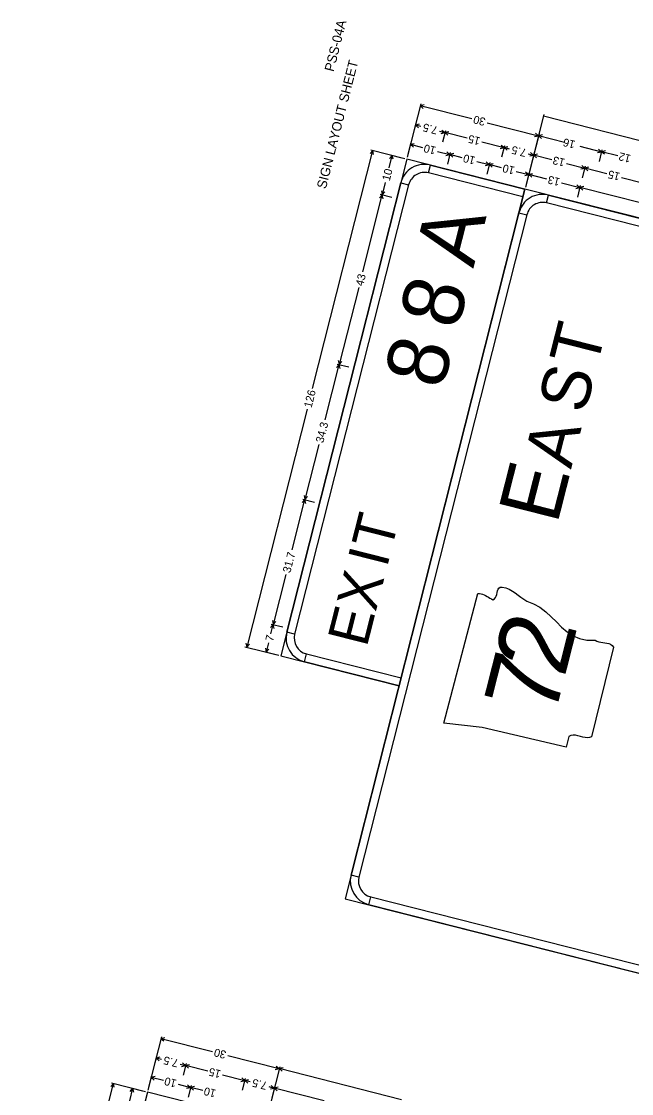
# Model space of a CAD drawing. Extents: x 670010 to 670131, y 737834 to 738002.
# Drawn here: x 670014.7 to 670052.3, y 737936.3 to 738002.2 of the extents above; entities that cross this region are included whole.
import ezdxf

# ---------------------------------------------------------------- set-up
doc = ezdxf.new("R2010")
doc.units = 0
doc.layers.add('R_Border', color=7, linetype='Continuous')
doc.layers.add('R_SIGN', color=7, linetype='Continuous')

msp = doc.modelspace()

# ---------------------------------------------------------------- linework, layer by layer
at = {"layer": 'R_SIGN'}
for p, q in [((670039.295, 737997.146), (670038.463, 737993.866)), ((670039.505, 737997.079), (670039.265, 737997.027)), ((670042.428, 737996.224), (670039.265, 737997.027)), ((670039.451, 737996.866), (670039.265, 737997.027)), ((670043.371, 737995.985), (670046.535, 737995.183)), ((670046.867, 737996.495), (670045.733, 737992.023)), ((670065.094, 737991.745), (670046.837, 737996.376)), ((670038.993, 737995.953), (670038.811, 737995.238)), ((670039.203, 737995.887), (670038.962, 737995.834)), ((670039.302, 737995.748), (670038.962, 737995.834)), ((670039.149, 737995.673), (670038.962, 737995.834)), ((670040.44, 737995.459), (670040.78, 737995.373)), ((670040.54, 737995.321), (670040.78, 737995.373)), ((670040.594, 737995.534), (670040.78, 737995.373)), ((670040.81, 737995.492), (670040.629, 737994.777)), ((670041.02, 737995.426), (670040.78, 737995.373)), ((670042.146, 737995.027), (670040.78, 737995.373)), ((670040.966, 737995.212), (670040.78, 737995.373)), ((670046.349, 737995.344), (670046.535, 737995.183)), ((670038.69, 737994.761), (670038.509, 737994.045)), ((670038.9, 737994.694), (670038.66, 737994.642)), ((670043.049, 737994.798), (670044.415, 737994.451)), ((670046.565, 737995.302), (670045.733, 737992.023)), ((670046.294, 737995.13), (670046.535, 737995.183)), ((670046.775, 737995.236), (670046.535, 737995.183)), ((670048.141, 737994.775), (670046.535, 737995.183)), ((670046.721, 737995.022), (670046.535, 737995.183)), ((670032.638, 737979.655), (670036.346, 737994.276)), ((670036.185, 737994.09), (670036.346, 737994.276)), ((670036.227, 737994.307), (670038.314, 737993.777)), ((670036.399, 737994.036), (670036.346, 737994.276)), ((670037.419, 737994.004), (670038.135, 737993.823)), ((670039.421, 737994.448), (670038.66, 737994.642)), ((670038.846, 737994.481), (670038.66, 737994.642)), ((670040.322, 737994.22), (670041.083, 737994.027)), ((670040.843, 737993.974), (670041.083, 737994.027)), ((670040.897, 737994.188), (670041.083, 737994.027)), ((670041.113, 737994.146), (670040.932, 737993.431)), ((670041.324, 737994.08), (670041.083, 737994.027)), ((670041.845, 737993.834), (670041.083, 737994.027)), ((670041.269, 737993.866), (670041.083, 737994.027)), ((670044.174, 737994.399), (670044.415, 737994.451)), ((670044.229, 737994.612), (670044.415, 737994.451)), ((670044.445, 737994.57), (670044.264, 737993.855)), ((670044.445, 737994.57), (670044.264, 737993.855)), ((670044.655, 737994.504), (670044.415, 737994.451)), ((670044.755, 737994.365), (670044.415, 737994.451)), ((670044.601, 737994.291), (670044.415, 737994.451)), ((670045.892, 737994.077), (670046.232, 737993.99)), ((670045.992, 737993.938), (670046.232, 737993.99)), ((670046.046, 737994.151), (670046.232, 737993.99)), ((670046.262, 737994.109), (670046.081, 737993.394)), ((670046.262, 737994.109), (670046.081, 737993.394)), ((670046.473, 737994.043), (670046.232, 737993.99)), ((670047.353, 737993.706), (670046.232, 737993.99)), ((670046.418, 737993.83), (670046.232, 737993.99)), ((670049.079, 737994.538), (670050.406, 737994.201)), ((670050.165, 737994.148), (670050.406, 737994.201)), ((670050.219, 737994.362), (670050.406, 737994.201)), ((670050.436, 737994.32), (670050.254, 737993.605)), ((670050.646, 737994.254), (670050.406, 737994.201)), ((670051.411, 737993.946), (670050.406, 737994.201)), ((670050.592, 737994.04), (670050.406, 737994.201)), ((670038.433, 737993.747), (670030.689, 737963.214)), ((670037.346, 737993.213), (670037.539, 737993.974)), ((670037.378, 737993.788), (670037.539, 737993.974)), ((670037.591, 737993.734), (670037.539, 737993.974)), ((670045.703, 737991.903), (670038.433, 737993.747)), ((670039.764, 737992.894), (670039.887, 737993.378)), ((670042.745, 737993.605), (670043.506, 737993.412)), ((670043.266, 737993.36), (670043.506, 737993.412)), ((670043.32, 737993.573), (670043.506, 737993.412)), ((670043.537, 737993.532), (670043.355, 737992.816)), ((670043.537, 737993.532), (670043.355, 737992.816)), ((670043.747, 737993.465), (670043.506, 737993.412)), ((670044.268, 737993.219), (670043.506, 737993.412)), ((670043.693, 737993.252), (670043.506, 737993.412)), ((670048.256, 737993.477), (670049.376, 737993.193)), ((670049.19, 737993.354), (670049.376, 737993.193)), ((670045.168, 737992.991), (670045.93, 737992.798)), ((670045.689, 737992.745), (670045.93, 737992.798)), ((670045.744, 737992.958), (670045.93, 737992.798)), ((670045.96, 737992.917), (670045.779, 737992.201)), ((670045.96, 737992.917), (670045.779, 737992.201)), ((670046.17, 737992.85), (670045.93, 737992.798)), ((670047.05, 737992.514), (670045.93, 737992.798)), ((670046.116, 737992.637), (670045.93, 737992.798)), ((670049.136, 737993.14), (670049.376, 737993.193)), ((670049.406, 737993.312), (670049.225, 737992.597)), ((670049.617, 737993.245), (670049.376, 737993.193)), ((670050.742, 737992.846), (670049.376, 737993.193)), ((670049.563, 737993.032), (670049.376, 737993.193)), ((670037.117, 737992.312), (670036.924, 737991.551)), ((670038.064, 737992.293), (670038.549, 737992.17)), ((670047.953, 737992.285), (670049.074, 737992)), ((670048.888, 737992.161), (670049.074, 737992)), ((670049.104, 737992.12), (670048.922, 737991.404)), ((670049.314, 737992.053), (670049.074, 737992)), ((670051.645, 737992.617), (670053.011, 737992.271)), ((670045.703, 737991.903), (670034.64, 737948.284)), ((670035.724, 737986.819), (670036.924, 737991.551)), ((670036.763, 737991.365), (670036.924, 737991.551)), ((670036.805, 737991.581), (670037.52, 737991.399)), ((670036.805, 737991.581), (670037.52, 737991.399)), ((670036.872, 737991.791), (670036.924, 737991.551)), ((670037.085, 737991.737), (670036.924, 737991.551)), ((670036.977, 737991.31), (670036.924, 737991.551)), ((670037.959, 737961.37), (670045.703, 737991.903)), ((670083.506, 737982.316), (670045.703, 737991.903)), ((670047.034, 737991.05), (670047.157, 737991.535)), ((670048.833, 737991.948), (670049.074, 737992)), ((670052.961, 737991.015), (670049.074, 737992)), ((670049.26, 737991.84), (670049.074, 737992)), ((670045.334, 737990.449), (670045.819, 737990.326)), ((670035.478, 737985.851), (670034.278, 737981.119)), ((670033.418, 737977.729), (670034.278, 737981.119)), ((670034.118, 737980.932), (670034.278, 737981.119)), ((670034.159, 737981.149), (670034.875, 737980.967)), ((670034.226, 737981.359), (670034.278, 737981.119)), ((670034.439, 737981.305), (670034.278, 737981.119)), ((670034.331, 737980.878), (670034.278, 737981.119)), ((670032.311, 737978.365), (670028.602, 737963.743)), ((670033.033, 737976.209), (670032.173, 737972.819)), ((670032.121, 737973.059), (670032.173, 737972.819)), ((670032.334, 737973.005), (670032.173, 737972.819)), ((670031.392, 737969.737), (670032.173, 737972.819)), ((670032.013, 737972.633), (670032.173, 737972.819)), ((670032.054, 737972.849), (670032.77, 737972.668)), ((670032.226, 737972.578), (670032.173, 737972.819)), ((670031.007, 737968.219), (670030.225, 737965.137)), ((670040.721, 737959.068), (670042.797, 737967.042)), ((670042.797, 737967.042), (670042.901, 737967.041)), ((670042.797, 737967.042), (670042.797, 737967.042)), ((670042.901, 737967.041), (670043.002, 737967.024)), ((670043.002, 737967.024), (670043.098, 737966.996)), ((670043.098, 737966.996), (670043.192, 737966.96)), ((670043.936, 737966.883), (670043.966, 737966.991)), ((670043.966, 737966.991), (670043.99, 737967.101)), ((670043.99, 737967.101), (670044.015, 737967.207)), ((670044.015, 737967.207), (670044.05, 737967.301)), ((670044.05, 737967.301), (670044.104, 737967.377)), ((670044.104, 737967.377), (670044.182, 737967.428)), ((670044.182, 737967.428), (670044.295, 737967.443)), ((670044.295, 737967.443), (670044.527, 737967.388)), ((670044.527, 737967.388), (670044.736, 737967.304)), ((670044.736, 737967.304), (670044.928, 737967.197)), ((670044.928, 737967.197), (670045.105, 737967.075)), ((670045.105, 737967.075), (670045.279, 737966.946)), ((670043.192, 737966.96), (670043.284, 737966.915)), ((670043.284, 737966.915), (670043.372, 737966.867)), ((670043.372, 737966.867), (670043.462, 737966.813)), ((670043.462, 737966.813), (670043.548, 737966.761)), ((670043.548, 737966.761), (670043.634, 737966.71)), ((670043.634, 737966.71), (670043.721, 737966.661)), ((670043.721, 737966.661), (670043.822, 737966.711)), ((670043.822, 737966.711), (670043.891, 737966.788)), ((670043.891, 737966.788), (670043.936, 737966.883)), ((670045.279, 737966.946), (670045.45, 737966.815)), ((670045.45, 737966.815), (670045.627, 737966.689)), ((670045.627, 737966.689), (670045.813, 737966.577)), ((670045.813, 737966.577), (670046.013, 737966.481)), ((670046.013, 737966.481), (670046.234, 737966.414)), ((670046.234, 737966.414), (670046.624, 737966.196)), ((670046.624, 737966.196), (670046.977, 737965.924)), ((670046.977, 737965.924), (670047.309, 737965.619)), ((670030.064, 737964.951), (670030.225, 737965.137)), ((670030.081, 737964.569), (670030.225, 737965.137)), ((670030.106, 737965.167), (670030.821, 737964.986)), ((670030.172, 737965.377), (670030.225, 737965.137)), ((670030.386, 737965.323), (670030.225, 737965.137)), ((670030.277, 737964.897), (670030.225, 737965.137)), ((670047.309, 737965.619), (670047.633, 737965.298)), ((670047.633, 737965.298), (670047.956, 737964.983)), ((670031.543, 737964.545), (670031.058, 737964.668)), ((670047.956, 737964.983), (670048.294, 737964.693)), ((670048.294, 737964.693), (670048.657, 737964.45)), ((670048.657, 737964.45), (670049.058, 737964.27)), ((670028.483, 737963.773), (670030.57, 737963.244)), ((670028.55, 737963.983), (670028.602, 737963.743)), ((670028.763, 737963.929), (670028.602, 737963.743)), ((670029.742, 737963.681), (670029.795, 737963.441)), ((670029.939, 737964.008), (670029.795, 737963.441)), ((670049.058, 737964.27), (670049.506, 737964.174)), ((670049.506, 737964.174), (670050.015, 737964.185)), ((670051.141, 737963.753), (670049.794, 737958.233)), ((670050.015, 737964.185), (670050.123, 737964.116)), ((670050.123, 737964.116), (670050.241, 737964.071)), ((670050.241, 737964.071), (670050.363, 737964.044)), ((670050.363, 737964.044), (670050.49, 737964.028)), ((670050.49, 737964.028), (670050.615, 737964.014)), ((670050.615, 737964.014), (670050.738, 737963.998)), ((670050.738, 737963.998), (670050.857, 737963.971)), ((670050.857, 737963.971), (670050.962, 737963.926)), ((670050.962, 737963.926), (670051.06, 737963.856)), ((670051.06, 737963.856), (670051.141, 737963.753)), ((670029.675, 737963.471), (670030.391, 737963.289)), ((670029.955, 737963.627), (670029.795, 737963.441)), ((670030.689, 737963.214), (670037.959, 737961.37)), ((670032.143, 737962.845), (670032.266, 737963.33)), ((670037.959, 737961.37), (670037.959, 737961.37)), ((670043.074, 737958.815), (670040.721, 737959.068)), ((670048.239, 737957.602), (670043.074, 737958.815)), ((670048.401, 737958.244), (670048.239, 737957.602)), ((670048.53, 737958.311), (670048.401, 737958.244)), ((670048.667, 737958.336), (670048.53, 737958.311)), ((670048.81, 737958.33), (670048.667, 737958.336)), ((670048.96, 737958.303), (670048.81, 737958.33)), ((670049.109, 737958.264), (670048.96, 737958.303)), ((670049.26, 737958.222), (670049.109, 737958.264)), ((670049.404, 737958.187), (670049.26, 737958.222)), ((670049.543, 737958.172), (670049.404, 737958.187)), ((670049.675, 737958.183), (670049.543, 737958.172)), ((670049.794, 737958.233), (670049.675, 737958.183)), ((670035.494, 737949.615), (670035.009, 737949.738)), ((670034.64, 737948.284), (670072.443, 737938.697)), ((670036.094, 737947.916), (670036.217, 737948.4)), ((670023.351, 737939.8), (670022.52, 737936.52)), ((670023.561, 737939.733), (670023.321, 737939.68)), ((670026.485, 737938.878), (670023.321, 737939.68)), ((670023.507, 737939.52), (670023.321, 737939.68)), ((670027.427, 737938.639), (670030.591, 737937.837)), ((670023.049, 737938.607), (670022.867, 737937.892)), ((670023.259, 737938.541), (670023.019, 737938.488)), ((670023.359, 737938.402), (670023.019, 737938.488)), ((670023.205, 737938.327), (670023.019, 737938.488)), ((670024.496, 737938.113), (670024.836, 737938.027)), ((670024.596, 737937.974), (670024.836, 737938.027)), ((670024.65, 737938.188), (670024.836, 737938.027)), ((670024.866, 737938.146), (670024.685, 737937.431)), ((670025.076, 737938.08), (670024.836, 737938.027)), ((670026.202, 737937.681), (670024.836, 737938.027)), ((670025.022, 737937.866), (670024.836, 737938.027)), ((670030.405, 737937.998), (670030.591, 737937.837)), ((670022.746, 737937.415), (670022.565, 737936.699)), ((670022.957, 737937.348), (670022.716, 737937.295)), ((670027.105, 737937.452), (670028.471, 737937.105)), ((670030.621, 737937.956), (670029.789, 737934.676)), ((670030.621, 737937.956), (670029.789, 737934.676)), ((670030.351, 737937.784), (670030.591, 737937.837)), ((670030.831, 737937.889), (670030.591, 737937.837)), ((670038.11, 737935.93), (670030.591, 737937.837)), ((670030.777, 737937.676), (670030.591, 737937.837)), ((670016.694, 737922.309), (670020.402, 737936.93)), ((670020.242, 737936.744), (670020.402, 737936.93)), ((670020.283, 737936.961), (670022.37, 737936.431)), ((670020.455, 737936.69), (670020.402, 737936.93)), ((670021.476, 737936.658), (670022.191, 737936.477)), ((670023.478, 737937.102), (670022.716, 737937.295)), ((670022.902, 737937.135), (670022.716, 737937.295)), ((670024.378, 737936.874), (670025.14, 737936.681)), ((670024.899, 737936.628), (670025.14, 737936.681)), ((670024.953, 737936.842), (670025.14, 737936.681)), ((670025.17, 737936.8), (670024.988, 737936.084)), ((670025.38, 737936.733), (670025.14, 737936.681)), ((670025.901, 737936.488), (670025.14, 737936.681)), ((670025.326, 737936.52), (670025.14, 737936.681)), ((670028.231, 737937.053), (670028.471, 737937.105)), ((670028.285, 737937.266), (670028.471, 737937.105)), ((670028.501, 737937.224), (670028.32, 737936.509)), ((670028.501, 737937.224), (670028.32, 737936.509)), ((670028.711, 737937.158), (670028.471, 737937.105)), ((670028.811, 737937.019), (670028.471, 737937.105)), ((670028.657, 737936.944), (670028.471, 737937.105)), ((670029.949, 737936.73), (670030.288, 737936.644)), ((670030.102, 737936.805), (670030.288, 737936.644)), ((670030.319, 737936.763), (670030.137, 737936.048)), ((670030.319, 737936.763), (670030.137, 737936.048)), ((670030.529, 737936.697), (670030.288, 737936.644)), ((670022.489, 737936.401), (670014.745, 737905.868)), ((670021.402, 737935.866), (670021.595, 737936.628)), ((670021.434, 737936.442), (670021.595, 737936.628)), ((670021.647, 737936.388), (670021.595, 737936.628)), ((670029.759, 737934.557), (670022.489, 737936.401)), ((670030.048, 737936.592), (670030.288, 737936.644)), ((670033.363, 737935.865), (670030.288, 737936.644)), ((670030.475, 737936.483), (670030.288, 737936.644))]:
    msp.add_line(p, q, dxfattribs=at)
for points in [[(670045.58, 737991.419), (670039.764, 737992.894), (670039.887, 737993.378), (670045.703, 737991.903), (670045.58, 737991.419)], [(670038.549, 737992.17), (670031.543, 737964.545), (670031.058, 737964.668), (670038.064, 737992.293), (670038.549, 737992.17)], [(670081.929, 737982.2), (670047.034, 737991.05), (670047.157, 737991.535), (670082.052, 737982.684), (670081.929, 737982.2)], [(670045.819, 737990.326), (670035.494, 737949.615), (670035.009, 737949.738), (670045.334, 737990.449), (670045.819, 737990.326)], [(670032.266, 737963.33), (670038.082, 737961.855), (670037.959, 737961.37), (670032.143, 737962.845), (670032.266, 737963.33)], [(670036.217, 737948.4), (670071.112, 737939.55), (670070.989, 737939.065), (670036.094, 737947.916), (670036.217, 737948.4)]]:
    msp.add_lwpolyline(points, close=True, dxfattribs=at)
for centre, radius, start, end in [((670039.518, 737991.924), 1.5, 75.76855, 165.76876), ((670039.518, 737991.924), 1, 75.76855, 165.76876), ((670046.788, 737990.081), 1.5, 75.76855, 165.76876), ((670046.788, 737990.081), 1, 75.76855, 165.76876), ((670032.512, 737964.299), 1.5, 165.76876, 255.7684), ((670032.512, 737964.299), 1, 165.76876, 255.7684), ((670036.463, 737949.37), 1.5, 165.76876, 255.7684), ((670036.463, 737949.37), 1, 165.76876, 255.7684)]:
    msp.add_arc(centre, radius, start, end, dxfattribs=at)

# ---------------------------------------------------------------- texts
at = {"layer": 'R_Border'}
for s, height, p in [('PSS-04A', 0.5861, (670033.937, 737999.084)), ('SIGN LAYOUT SHEET', 0.5862, (670033.462, 737991.883))]:
    msp.add_text(s, height=height, rotation=75.76855, dxfattribs=at).set_placement(p)
at = {"layer": 'R_SIGN'}
for s, height, rotation, p in [('30', 0.4921, 165.76876, (670043.312, 737996.254)), ('7.5', 0.4921, 165.76876, (670040.381, 737995.728)), ('10', 0.4921, 165.76876, (670040.263, 737994.489)), ('15', 0.4921, 165.76876, (670042.99, 737995.066)), ('16', 0.4921, 165.76876, (670048.83, 737994.855)), ('10', 0.4921, 165.76876, (670042.686, 737993.874)), ('7.5', 0.4921, 165.76876, (670045.833, 737994.345)), ('12', 0.4921, 165.76876, (670052.25, 737993.987)), ('10', 0.4921, 165.76876, (670045.11, 737993.26)), ('13', 0.4921, 165.76876, (670048.197, 737993.746)), ('10', 0.4921, 75.76855, (670037.386, 737992.371)), ('13', 0.4921, 165.76876, (670047.894, 737992.553)), ('15', 0.4921, 165.76876, (670051.586, 737992.886)), ('A', 3.75, 75.76855, (670042.524, 737986.997)), ('43', 0.4921, 75.76855, (670035.747, 737985.909)), ('8', 3.75, 75.76855, (670041.556, 737983.18)), ('T', 3, 75.76855, (670050.093, 737980.816)), ('8', 3.75, 75.76855, (670040.625, 737979.509)), ('S', 3, 75.76855, (670049.385, 737978.025)), ('126', 0.4921, 75.76855, (670032.579, 737978.424)), ('34.3', 0.4921, 75.76855, (670033.302, 737976.267)), ('A', 3, 75.76855, (670048.53, 737974.651)), ('E', 3.75, 75.76855, (670047.675, 737971.232)), ('T', 2.5, 75.76855, (670037.459, 737969.57)), ('31.7', 0.4921, 75.76855, (670031.275, 737968.278)), ('I', 2.5, 75.76855, (670037.207, 737968.575)), ('X', 2.5, 75.76855, (670036.521, 737965.871)), ('E', 2.5, 75.76855, (670035.966, 737963.681)), ('2', 4.5, 75.76855, (670048.123, 737961.812)), ('7', 0.492, 75.76855, (670030.207, 737964.067)), ('7', 4.5, 75.76855, (670047.504, 737959.37)), ('30', 0.4921, 165.76876, (670027.369, 737938.908)), ('7.5', 0.4921, 165.76876, (670024.437, 737938.382)), ('15', 0.4921, 165.76876, (670027.046, 737937.72)), ('10', 0.4921, 165.76876, (670024.319, 737937.143)), ('10', 0.4921, 165.76876, (670026.743, 737936.528)), ('7.5', 0.4921, 165.76876, (670029.89, 737936.999))]:
    msp.add_text(s, height=height, rotation=rotation, dxfattribs=at).set_placement(p)

doc.saveas('drawing.dxf')
